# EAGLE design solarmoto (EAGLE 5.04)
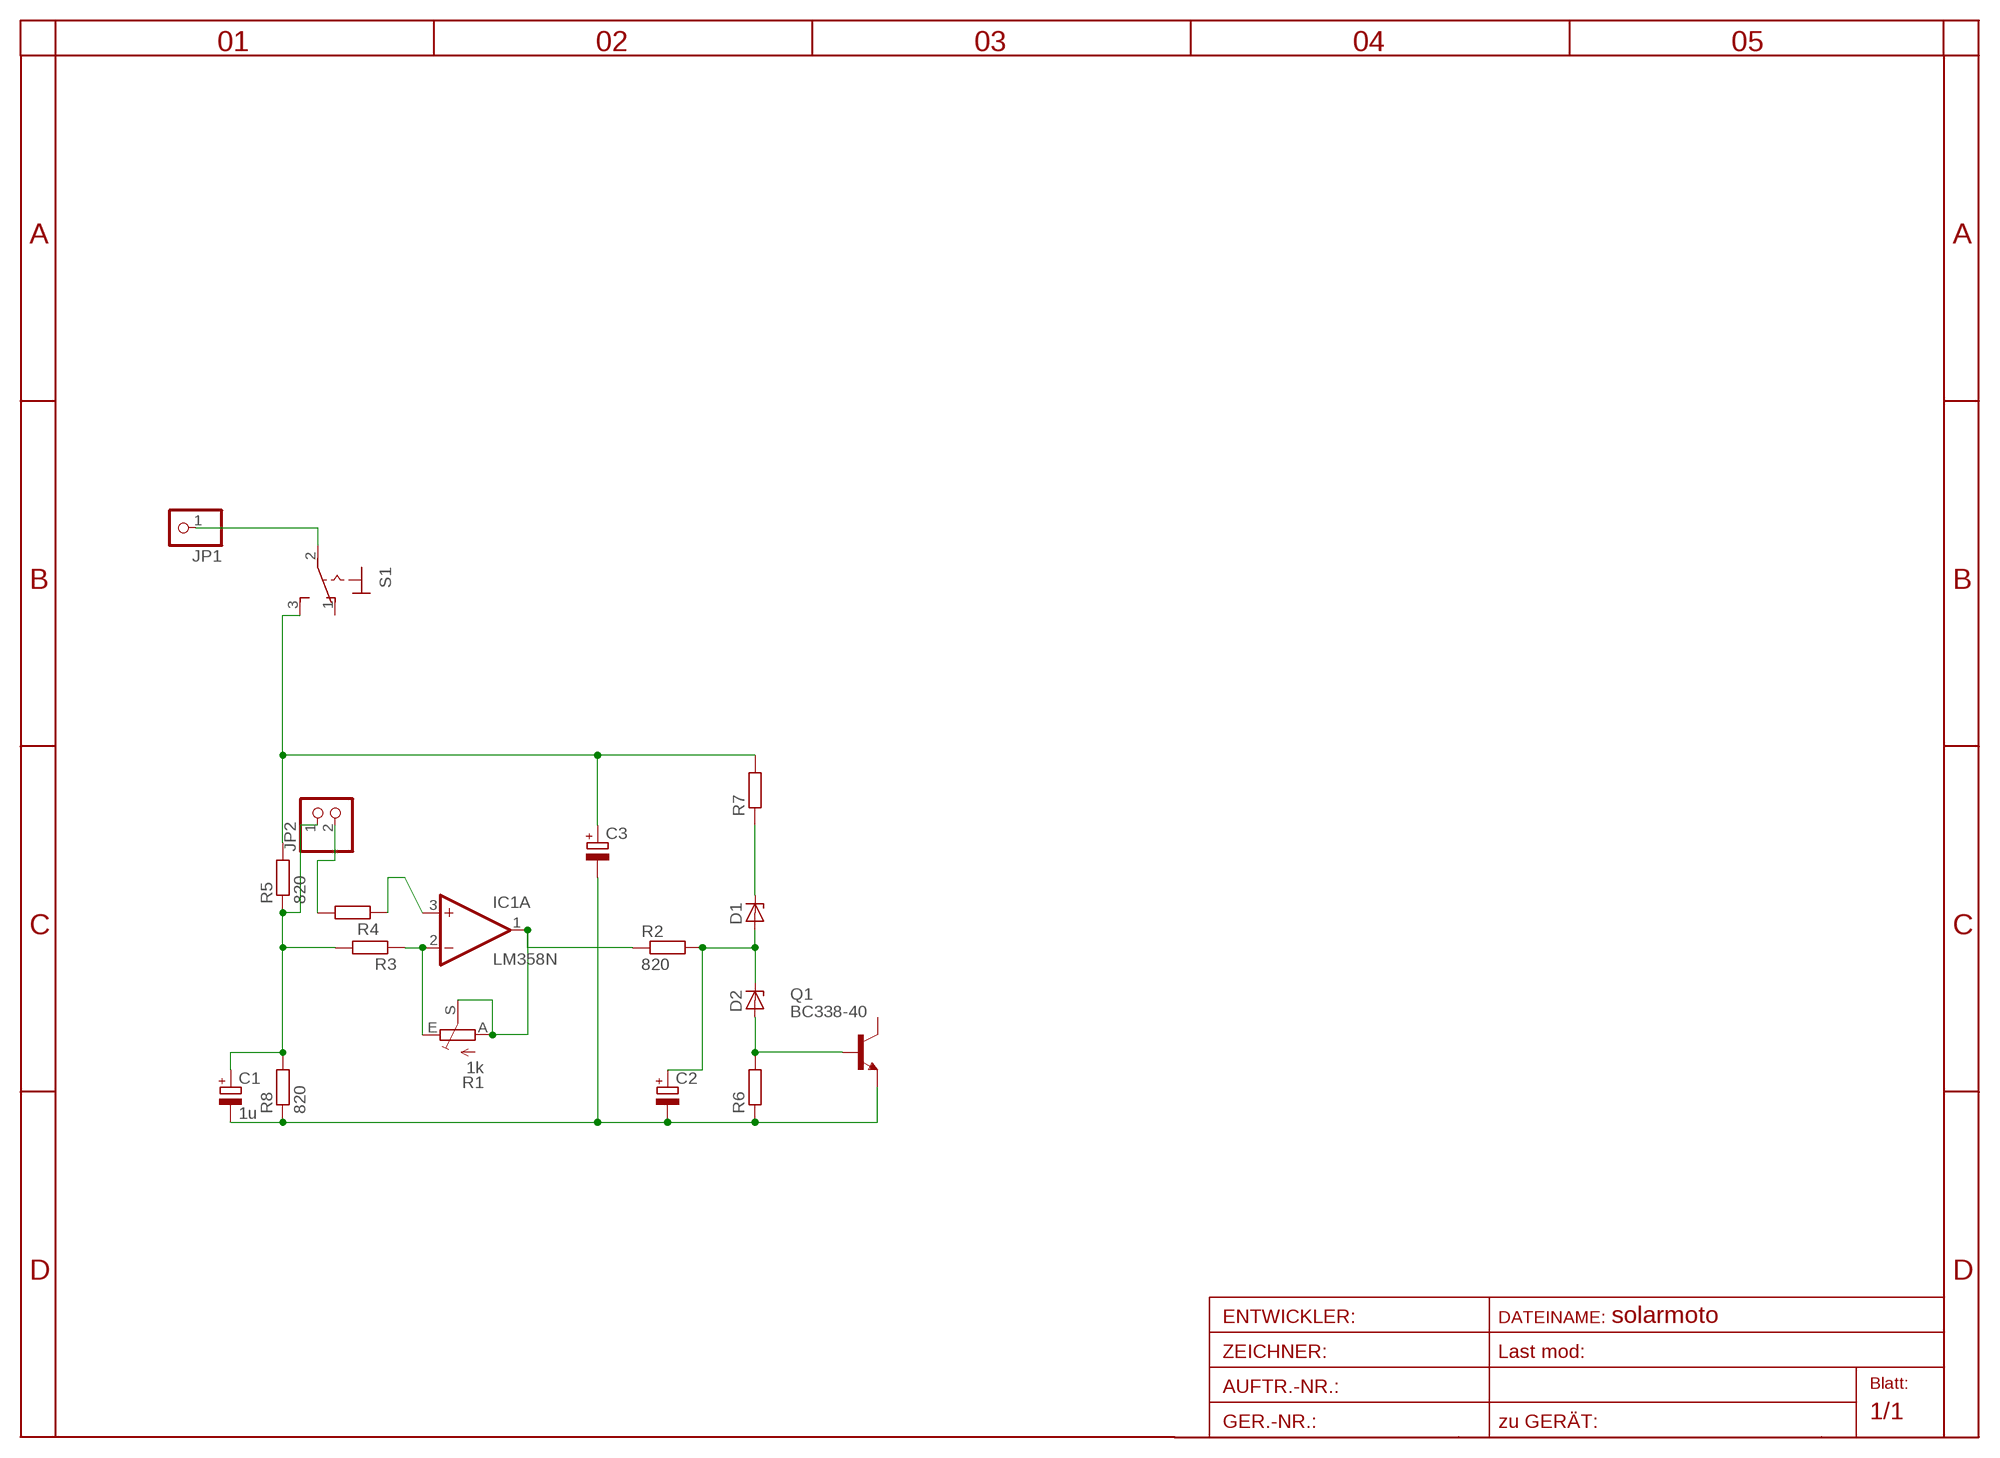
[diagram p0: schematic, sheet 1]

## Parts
C1  1u  CPOL-EUE5-8.5  [E5-8,5]
C2  CPOL-EUE5-8.5  [E5-8,5]
C3  CPOL-EUE2-5  [E2-5]
D1  ZENER-DIODEZD-7.5  [ZDIO-7.5]
D2  ZENER-DIODEZD-7.5  [ZDIO-7.5]
IC1  LM358N  [DIL08]
JP1  PINHD-1X1  [1X01]
JP2  PINHD-1X2  [1X02]
Q1  BC338-40  [TO92-EBC]
R1  1k  TRIM_EU-CA6V  [CA6V]
R2  820  R-EU_0207/10  [0207/10]
R3  R-EU_0207/10  [0207/10]
R4  R-EU_0207/10  [0207/10]
R5  820  R-EU_0207/10  [0207/10]
R6  R-EU_0207/10  [0207/10]
R7  R-EU_0207/10  [0207/10]
R8  820  R-EU_0207/10  [0207/10]
S1  320-916  [320-916]

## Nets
N$1: IC1.2(A:-IN) R1.E R3.1
N$2: C1.+ JP2.1 R3.2 R5.1 R8.2
N$4: C2.+ D1.A D2.C R2.2
N$5: D2.A Q1.B R6.2
N$6: D1.C R7.1
N$7: IC1.1(A:OUT) R1.A R1.S R2.1
N$8: IC1.3(A:+IN) R4.1
N$9: JP2.2 R4.2
N$10: JP1.1 S1.2(P)
V+: C3.+ R5.2 R7.2 S1.3(S)
V-: C1.- C2.- C3.- Q1.E R6.1 R8.1
Unconnected: IC1.5(B:+IN) IC1.6(B:-IN) IC1.7(B:OUT) Q1.C S1.1(O)

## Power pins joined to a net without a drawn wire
V+: IC1.8(P:V+)
V-: IC1.4(P:V-)

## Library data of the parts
C1-C3 = rcl-2:CPOL-EU: POLARIZED CAPACITOR, European symbol
D1 D2 = diode-1:ZENER-DIODE: Z-Diode
IC1 = linear:LM358: OP AMP also LM158; LM258; LM2904 Source: http://cache.national.com/ds/LM/LM158.pdf
JP1 = pinhead:PINHD-1X1: PIN HEADER
JP2 = pinhead:PINHD-1X2: PIN HEADER
Q1 = transistor-npn:BC338*: NPN Transistor
R1 = pot:TRIM_EU-: POTENTIOMETER
R2-R8 = rcl-2:R-EU_: RESISTOR, European symbol
S1 = switch:320-916: TOGGLE SWITCH distributor RS Components

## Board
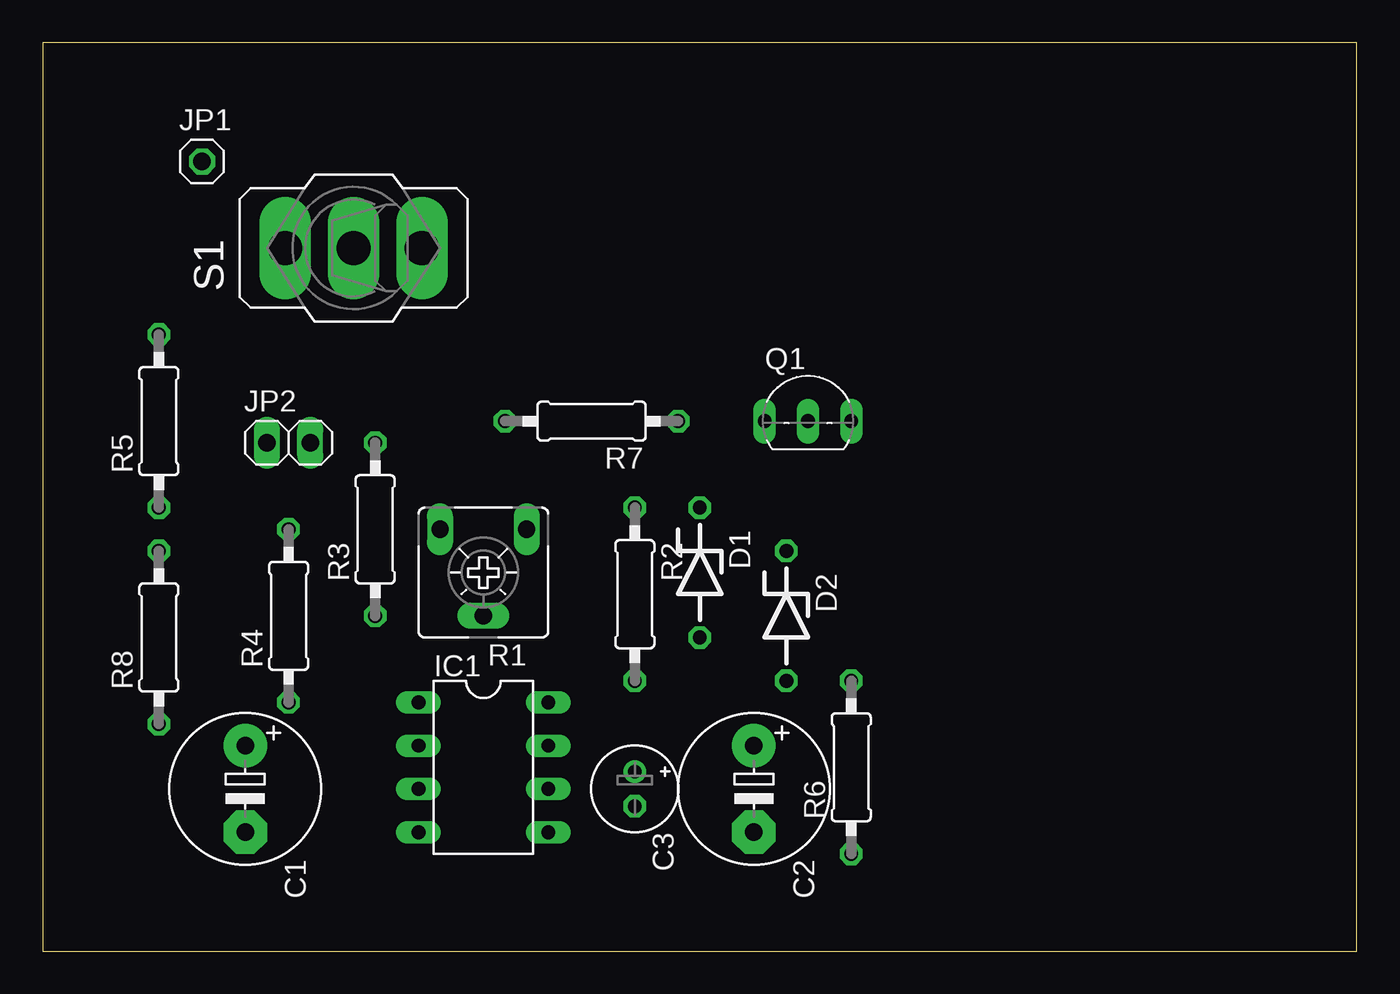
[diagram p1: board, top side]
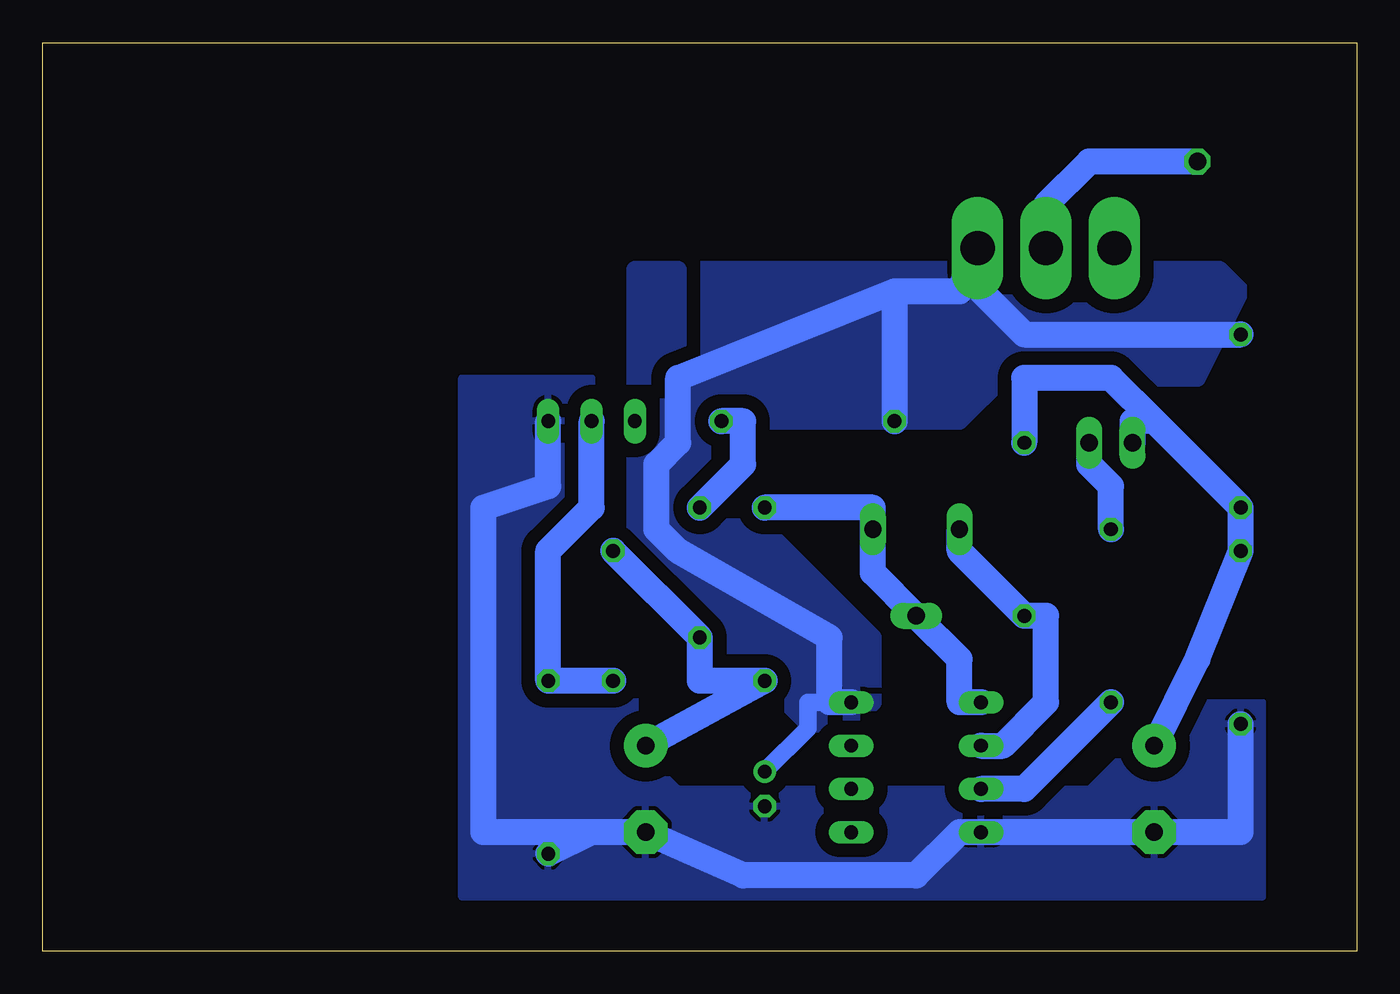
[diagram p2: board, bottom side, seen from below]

Size 77.14 x 53.33 mm. Coordinates in mm from the lower left corner, seen from the top.
Outline: 0,0 77.14,0 77.14,53.33 0,53.33 0,0
Copper layers (1*16): Top 0.035mm / dielectric 1.5mm / Bottom 0.035mm
Design rules "default *": minimum track width 60mil, minimum drill 24mil, track to track 20mil, track to pad 20mil, pad to pad 8mil, via to via 8mil, smd to smd 8mil, copper to edge 40mil, drill to drill 8mil, minimum pad ring 10mil, minimum via ring 8mil, stop-mask expansion 4mil, vias tented up to drill 0mil, thermal gap 10mil

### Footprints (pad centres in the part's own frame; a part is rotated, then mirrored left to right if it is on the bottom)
E5-8,5 = drill 1.016 pad 2.54 round: + -2.54,0 | drill 1.016 pad 2.54 octagon: - 2.54,0
E2-5 = drill 0.813 pad 1.27 round: + -1.016,0 | drill 0.813 pad 1.27 octagon: - 1.016,0
ZDIO-7.5 = drill 0.813 octagon: A 3.81,0; C -3.81,0
DIL08 = drill 0.813 long: 1 -3.81,-3.81; 2 -1.27,-3.81; 3 1.27,-3.81; 4 3.81,-3.81; 5 3.81,3.81; 6 1.27,3.81; 7 -1.27,3.81; 8 -3.81,3.81
1X01 = drill 1.016 octagon: 1 0,0
1X02 = drill 1.016 long: 1 -1.27,0; 2 1.27,0
TO92-EBC = drill 0.813 long: B 0,-1.27; C -2.54,-1.27; E 2.54,-1.27
CA6V = drill 1.016 long: A -2.54,-2.54; E 2.54,-2.54; S 0,2.54
0207/10 = drill 0.813 octagon: 1 -5.08,0; 2 5.08,0
320-916 = drill 2.007 long: 1 0,4.013; 2 0,0; 3 0,-4.013

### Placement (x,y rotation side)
C1  11.9,9.52 270 top
C2  41.74,9.52 270 top
C3  34.76,9.52 270 top
D1  38.57,22.22 270 top
D2  43.65,19.68 270 top
IC1  25.87,10.79 270 top
JP1  9.36,46.35 0 top
JP2  14.44,29.84 0 top
Q1  44.92,32.38 0 top
R1  25.87,22.22 180 top
R2  34.76,20.95 270 top
R3  19.52,24.76 90 top
R4  14.44,19.68 90 top
R5  6.82,31.11 90 top
R6  47.46,10.79 90 top
R7  32.22,31.11 180 top
R8  6.82,18.41 90 top
S1  18.25,41.27 90 top

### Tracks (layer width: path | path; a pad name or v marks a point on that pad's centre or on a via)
N$1
  Bottom 1.524: IC1.2 20.79,12.06 18.25,14.6 18.25,19.68 R3.1 23.33,23.49 R1.E
N$2
  Bottom 1.524: R3.2 19.52,33.65 14.44,33.65 11.9,31.11 | 11.9,31.11 R5.1 R8.2 9.36,17.14 C1.+ | 11.9,31.11 13.17,31.11 JP2.1
N$3
  pour Bottom (isolate 0.813): 42.38,29.84 39.84,32.38 39.84,40 42.38,40
N$4
  Bottom 1.524: D2.C D1.A 38.57,15.87 R2.2 C2.+
N$5
  Bottom 1.524: D2.A R6.2 47.46,23.49 44.92,26.03 Q1.B
N$6
  Bottom 1.524: D1.C 36.03,28.57 36.03,31.11 R7.1
N$7
  Bottom 1.524: R2.1 28.41,26.03 R1.A 28.41,22.22 R1.S 23.33,17.14 23.33,14.6 IC1.1
N$8
  Bottom 1.524: R4.1 19.52,9.52 IC1.3
N$9
  Bottom 1.524: R4.2 14.44,27.3 15.71,28.57 JP2.2
N$10
  Bottom 1.524: JP1.1 15.71,46.35 18.25,43.81 S1.2
V+
  Bottom 1.016: C3.+ 32.22,13.08 32.22,14.6 IC1.8
  Bottom 1.524: 27.14,38.73 23.33,38.73 S1.3 22.06,38.73 19.52,36.19 R5.2 | 27.14,38.73 39.84,33.65 39.84,29.84 41.11,28.57 41.11,24.76 39.84,23.49 30.95,18.41 30.95,14.6 IC1.8 | 27.14,38.73 R7.2
  pour Bottom (isolate 0.813, rank 3): 6.82,38.73 8.09,40 42.38,40 42.38,23.49 32.22,13.33 29.68,13.33 28.41,14.6 28.41,15.87 28.41,18.41 37.3,27.3 37.3,29.84 36.03,31.11 23.33,31.11 20.79,33.65 9.36,33.65
V-
  Bottom 1.524: 6.82,6.98 C1.- | 6.82,6.98 IC1.4 23.33,6.98 25.87,4.44 36.03,4.44 C2.- 44.92,6.98 | 6.82,6.98 R8.1 | 44.92,6.98 R6.1 | 44.92,6.98 51.27,6.98 51.27,26.03 47.46,27.3 Q1.E
  pour Bottom (isolate 0.813, rank 6): 5.55,14.6 5.55,3.17 52.54,3.17 52.54,33.65 44.92,33.65 44.92,32.38 42.38,29.84 42.38,12.06 39.84,9.52 15.71,9.52 10.63,14.6 8.09,14.6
